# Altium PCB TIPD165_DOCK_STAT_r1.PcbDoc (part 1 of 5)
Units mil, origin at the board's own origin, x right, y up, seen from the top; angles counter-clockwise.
Board outline 6950 x 2800 mil, 2 copper layers (Primary Side, Secondary Side), stack 12.7 mil thick; 32 components, 163 nets, 1211 pads, 80 vias.
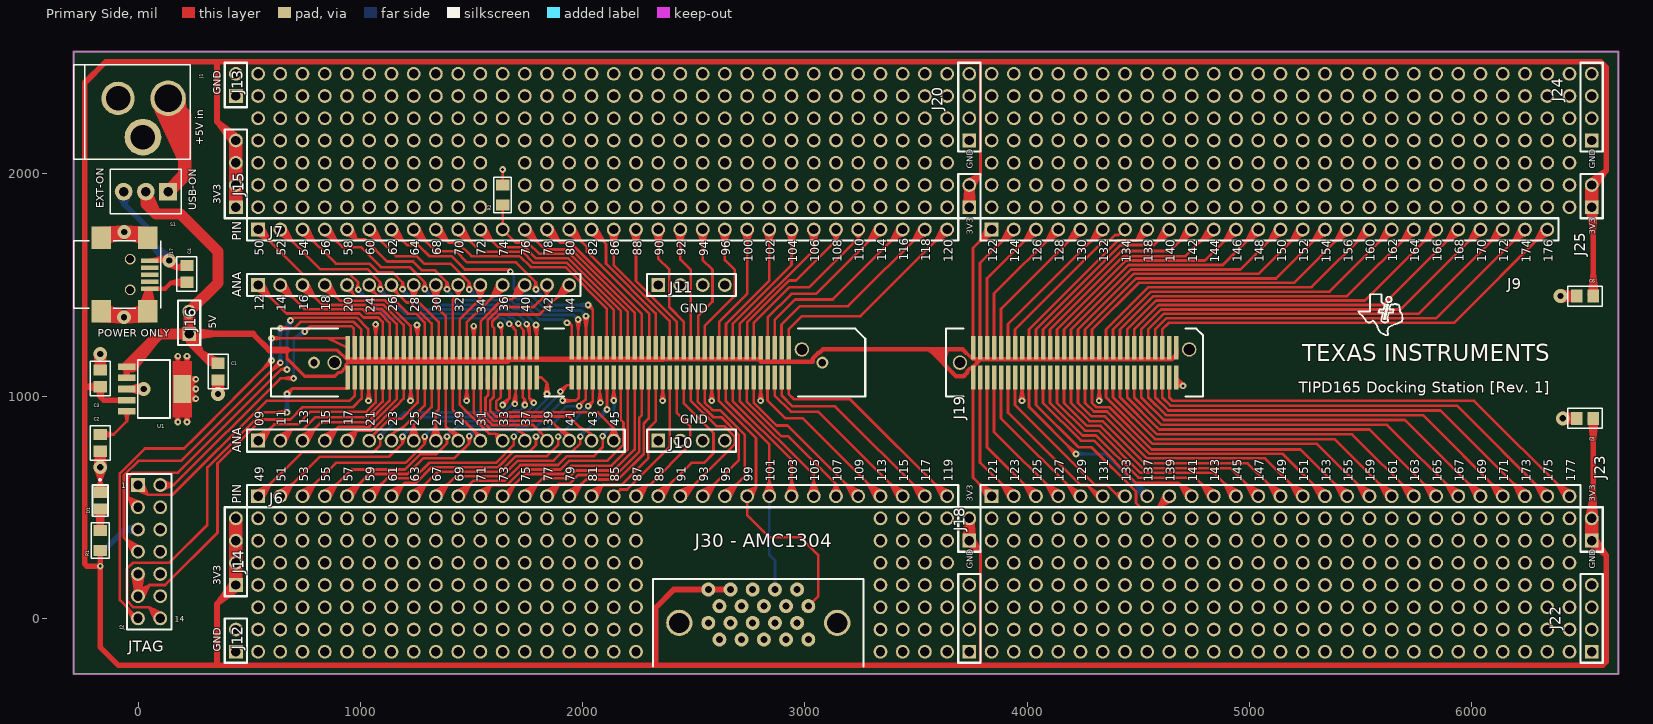
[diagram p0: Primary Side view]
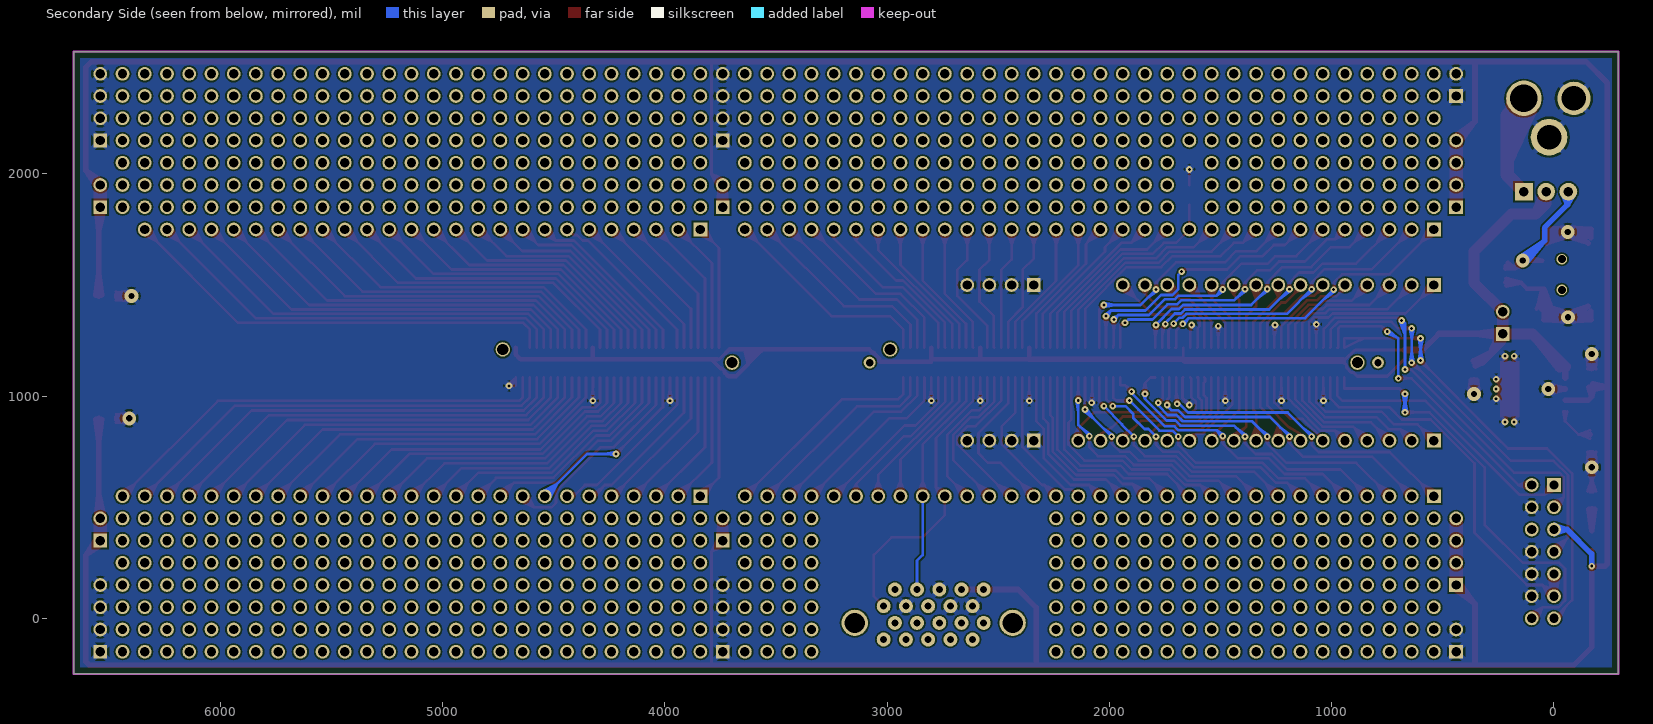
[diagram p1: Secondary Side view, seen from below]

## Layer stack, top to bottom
Primary Side: signal copper 1.35
Dielectric: dielectric 10, FR-4, Dk 4.3
Secondary Side: signal copper 1.35

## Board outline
-290,-250 6660,-250 6660,2550 -290,2550

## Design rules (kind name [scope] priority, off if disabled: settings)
Clearance "'Default' PADS rule_18" [All] p1: gap=7
Clearance "'Default' PADS rule_15" [IsVia vs IsVia] p2: gap=6
ComponentClearance "'Default' PADS rule_12" [All] p1: gap=6 collisioncheckmode=3 verticalgap=10 showdistances=FALSE
FlightTimeFalling "'Default' PADS rule_10" [All] p1: maximum=10.00
FlightTimeRising "'Default' PADS rule_9" [All] p1: maximum=10.00
Length "'Default' PADS rule_5" [All] p1: maxlimit=50000 minlimit=0
MatchedLengths "'Default' PADS rule_11" [InNetClass('All Nets')] p1: tolerance=200 checknetsindiffpair=TRUE checkdiffpairvsdiffpair=TRUE checkothers=TRUE
MaxMinImpedance "'Default' PADS rule_8" [All] p1: minimum=50.00 maximum=150.0
ParallelSegment "'Default' PADS rule_7" [All] p1: limit=1000 gap=200
ParallelSegment "'Default' PADS rule_6" [All] p2: limit=1000 gap=200
PlaneClearance "Power Plane Clearance for J8-25" [(Name='J8-25') Or (Name='J8-26') Or (Name='J8-27') Or (Name='J9-1') Or (Name='J9-2') Or (Name='J9-3') Or (Name='J9-4') Or (Name='J9-5') Or (Name='J9-6') Or (Name='J9-7') Or (Name='J9-8') Or (Name='J9-9') Or (Name='J9-10') Or (Name='J9-11') Or (Name='J9-12') Or (Name='J9-13') Or (Name='J9-14') Or (Name='J9-15') Or (Name='J9-16') Or (Name='J9-17') Or (Name='J9-18') Or (Name='J9-19') Or (Name='J9-20') Or (Name='J9-21') Or (Name='J9-22') Or (Name='J9-23') Or (Name='J9-24') Or (Name='J9-25') Or (Name='J9-26')] p1: clearance=20 // PAD - Power Plane Clearance
PlaneClearance "Power Plane Clearance for J7-3" [(Name='J7-3') Or (Name='J7-4') Or (Name='J7-5') Or (Name='J7-6') Or (Name='J7-7') Or (Name='J7-8') Or (Name='J7-9') Or (Name='J7-10') Or (Name='J7-11') Or (Name='J7-12') Or (Name='J7-13') Or (Name='J7-14') Or (Name='J7-15') Or (Name='J7-16') Or (Name='J7-17') Or (Name='J7-18') Or (Name='J7-19') Or (Name='J7-20') Or (Name='J7-21') Or (Name='J7-22') Or (Name='J7-23') Or (Name='J7-24') Or (Name='J7-25') Or (Name='J7-26') Or (Name='J7-27') Or (Name='J7-28') Or (Name='J7-29') Or (Name='J7-30') Or (Name='J7-31') Or (Name='J7-32') Or (Name='J8-1') Or (Name='J8-2') Or (Name='J8-3') Or (Name='J8-4') Or (Name='J8-5') Or (Name='J8-6') Or (Name='J8-7') Or (Name='J8-8') Or (Name='J8-9') Or (Name='J8-10') Or (Name='J8-11') Or (Name='J8-12') Or (Name='J8-13') Or (Name='J8-14') Or (Name='J8-15') Or (Name='J8-16') Or (Name='J8-17') Or (Name='J8-18') Or (Name='J8-19') Or (Name='J8-20') Or (Name='J8-21') Or (Name='J8-22') Or (Name='J8-23') Or (Name='J8-24')] p2: clearance=20 // PAD - Power Plane Clearance
PlaneClearance "Power Plane Clearance for J4-12" [(Name='J4-12') Or (Name='J4-13') Or (Name='J4-14') Or (Name='J4-15') Or (Name='J4-16') Or (Name='J4-17') Or (Name='J5-1') Or (Name='J5-2') Or (Name='J5-3') Or (Name='J5-4') Or (Name='J5-5') Or (Name='J5-6') Or (Name='J5-7') Or (Name='J5-8') Or (Name='J5-9') Or (Name='J5-10') Or (Name='J5-11') Or (Name='J5-12') Or (Name='J5-13') Or (Name='J5-14') Or (Name='J5-15') Or (Name='J6-1') Or (Name='J6-2') Or (Name='J6-3') Or (Name='J6-4') Or (Name='J6-5') Or (Name='J6-6') Or (Name='J6-7') Or (Name='J6-8') Or (Name='J6-9') Or (Name='J6-10') Or (Name='J6-11') Or (Name='J6-12') Or (Name='J6-13') Or (Name='J6-14') Or (Name='J6-15') Or (Name='J6-16') Or (Name='J6-17') Or (Name='J6-18') Or (Name='J6-19') Or (Name='J6-20') Or (Name='J6-21') Or (Name='J6-22') Or (Name='J6-23') Or (Name='J6-24') Or (Name='J6-25') Or (Name='J6-26') Or (Name='J6-27') Or (Name='J6-28') Or (Name='J6-29') Or (Name='J6-30') Or (Name='J6-31') Or (Name='J6-32') Or (Name='J7-1') Or (Name='J7-2')] p3: clearance=20 // PAD - Power Plane Clearance
PlaneClearance "Power Plane Clearance for J3-183" [(Name='J3-183') Or (Name='J3-184')] p4: clearance=10 // PAD - Power Plane Clearance
PlaneClearance "Power Plane Clearance for J29-155" [(Name='J29-155') Or (Name='J29-156') Or (Name='J29-157') Or (Name='J29-158') Or (Name='J29-159') Or (Name='J29-160') Or (Name='J29-161') Or (Name='J29-162') Or (Name='J29-163') Or (Name='J29-164') Or (Name='J29-165') Or (Name='J29-166') Or (Name='J29-167') Or (Name='J29-168') Or (Name='J29-169') Or (Name='J29-170') Or (Name='J29-171') Or (Name='J29-172') Or (Name='J29-173') Or (Name='J29-174') Or (Name='J29-175') Or (Name='J29-176') Or (Name='J29-177') Or (Name='J29-178') Or (Name='J29-179') Or (Name='J29-180') Or (Name='J29-181') Or (Name='J29-182') Or (Name='J29-183') Or (Name='J29-184') Or (Name='J29-185') Or (Name='J29-186') Or (Name='J29-187') Or (Name='J29-188') Or (Name='J29-189') Or (Name='J3-181') Or (Name='J3-182') Or (Name='J3-185') Or (Name='J3-186') Or (Name='J4-1') Or (Name='J4-2') Or (Name='J4-3') Or (Name='J4-4') Or (Name='J4-5') Or (Name='J4-6') Or (Name='J4-7') Or (Name='J4-8') Or (Name='J4-9') Or (Name='J4-10') Or (Name='J4-11')] p5: clearance=20 // PAD - Power Plane Clearance
PlaneClearance "Power Plane Clearance for J29-107" [(Name='J29-107') Or (Name='J29-108') Or (Name='J29-109') Or (Name='J29-110') Or (Name='J29-111') Or (Name='J29-112') Or (Name='J29-113') Or (Name='J29-114') Or (Name='J29-115') Or (Name='J29-116') Or (Name='J29-117') Or (Name='J29-118') Or (Name='J29-119') Or (Name='J29-120') Or (Name='J29-121') Or (Name='J29-122') Or (Name='J29-123') Or (Name='J29-124') Or (Name='J29-125') Or (Name='J29-126') Or (Name='J29-127') Or (Name='J29-128') Or (Name='J29-129') Or (Name='J29-130') Or (Name='J29-131') Or (Name='J29-132') Or (Name='J29-133') Or (Name='J29-134') Or (Name='J29-135') Or (Name='J29-136') Or (Name='J29-137') Or (Name='J29-138') Or (Name='J29-139') Or (Name='J29-140') Or (Name='J29-141') Or (Name='J29-142') Or (Name='J29-143') Or (Name='J29-144') Or (Name='J29-145') Or (Name='J29-146') Or (Name='J29-147') Or (Name='J29-148') Or (Name='J29-149') Or (Name='J29-150') Or (Name='J29-151') Or (Name='J29-152') Or (Name='J29-153') Or (Name='J29-154')] p6: clearance=20 // PAD - Power Plane Clearance
PlaneClearance "Power Plane Clearance for J29-57" [(Name='J29-57') Or (Name='J29-58') Or (Name='J29-59') Or (Name='J29-60') Or (Name='J29-61') Or (Name='J29-62') Or (Name='J29-63') Or (Name='J29-64') Or (Name='J29-65') Or (Name='J29-66') Or (Name='J29-67') Or (Name='J29-68') Or (Name='J29-69') Or (Name='J29-70') Or (Name='J29-71') Or (Name='J29-72') Or (Name='J29-73') Or (Name='J29-74') Or (Name='J29-75') Or (Name='J29-76') Or (Name='J29-77') Or (Name='J29-78') Or (Name='J29-79') Or (Name='J29-80') Or (Name='J29-81') Or (Name='J29-82') Or (Name='J29-83') Or (Name='J29-84') Or (Name='J29-85') Or (Name='J29-86') Or (Name='J29-87') Or (Name='J29-88') Or (Name='J29-89') Or (Name='J29-90') Or (Name='J29-91') Or (Name='J29-92') Or (Name='J29-93') Or (Name='J29-94') Or (Name='J29-95') Or (Name='J29-96') Or (Name='J29-97') Or (Name='J29-98') Or (Name='J29-99') Or (Name='J29-100') Or (Name='J29-101') Or (Name='J29-102') Or (Name='J29-103') Or (Name='J29-104') Or (Name='J29-105') Or (Name='J29-106')] p7: clearance=20 // PAD - Power Plane Clearance
PlaneClearance "Power Plane Clearance for J29-6" [(Name='J29-6') Or (Name='J29-7') Or (Name='J29-8') Or (Name='J29-9') Or (Name='J29-10') Or (Name='J29-11') Or (Name='J29-12') Or (Name='J29-13') Or (Name='J29-14') Or (Name='J29-15') Or (Name='J29-16') Or (Name='J29-17') Or (Name='J29-18') Or (Name='J29-19') Or (Name='J29-20') Or (Name='J29-21') Or (Name='J29-22') Or (Name='J29-23') Or (Name='J29-24') Or (Name='J29-25') Or (Name='J29-26') Or (Name='J29-27') Or (Name='J29-28') Or (Name='J29-29') Or (Name='J29-30') Or (Name='J29-31') Or (Name='J29-32') Or (Name='J29-33') Or (Name='J29-34') Or (Name='J29-35') Or (Name='J29-36') Or (Name='J29-37') Or (Name='J29-38') Or (Name='J29-39') Or (Name='J29-40') Or (Name='J29-41') Or (Name='J29-42') Or (Name='J29-43') Or (Name='J29-44') Or (Name='J29-45') Or (Name='J29-46') Or (Name='J29-47') Or (Name='J29-48') Or (Name='J29-49') Or (Name='J29-50') Or (Name='J29-51') Or (Name='J29-52') Or (Name='J29-53') Or (Name='J29-54') Or (Name='J29-55') Or (Name='J29-56')] p8: clearance=20 // PAD - Power Plane Clearance
PlaneClearance "Power Plane Clearance for J28-146" [(Name='J28-146') Or (Name='J28-147') Or (Name='J28-148') Or (Name='J28-149') Or (Name='J28-150') Or (Name='J28-151') Or (Name='J28-152') Or (Name='J28-153') Or (Name='J28-154') Or (Name='J28-155') Or (Name='J28-156') Or (Name='J28-157') Or (Name='J28-158') Or (Name='J28-159') Or (Name='J28-160') Or (Name='J28-161') Or (Name='J28-162') Or (Name='J28-163') Or (Name='J28-164') Or (Name='J28-165') Or (Name='J28-166') Or (Name='J28-167') Or (Name='J28-168') Or (Name='J28-169') Or (Name='J28-170') Or (Name='J28-171') Or (Name='J28-172') Or (Name='J28-173') Or (Name='J28-174') Or (Name='J28-175') Or (Name='J28-176') Or (Name='J28-177') Or (Name='J28-178') Or (Name='J28-179') Or (Name='J28-180') Or (Name='J28-181') Or (Name='J28-182') Or (Name='J28-183') Or (Name='J28-184') Or (Name='J28-185') Or (Name='J28-186') Or (Name='J28-187') Or (Name='J28-188') Or (Name='J28-189') Or (Name='J29-1') Or (Name='J29-2') Or (Name='J29-3') Or (Name='J29-4') Or (Name='J29-5')] p9: clearance=20 // PAD - Power Plane Clearance
PlaneClearance "Power Plane Clearance for J28-98" [(Name='J28-98') Or (Name='J28-99') Or (Name='J28-100') Or (Name='J28-101') Or (Name='J28-102') Or (Name='J28-103') Or (Name='J28-104') Or (Name='J28-105') Or (Name='J28-106') Or (Name='J28-107') Or (Name='J28-108') Or (Name='J28-109') Or (Name='J28-110') Or (Name='J28-111') Or (Name='J28-112') Or (Name='J28-113') Or (Name='J28-114') Or (Name='J28-115') Or (Name='J28-116') Or (Name='J28-117') Or (Name='J28-118') Or (Name='J28-119') Or (Name='J28-120') Or (Name='J28-121') Or (Name='J28-122') Or (Name='J28-123') Or (Name='J28-124') Or (Name='J28-125') Or (Name='J28-126') Or (Name='J28-127') Or (Name='J28-128') Or (Name='J28-129') Or (Name='J28-130') Or (Name='J28-131') Or (Name='J28-132') Or (Name='J28-133') Or (Name='J28-134') Or (Name='J28-135') Or (Name='J28-136') Or (Name='J28-137') Or (Name='J28-138') Or (Name='J28-139') Or (Name='J28-140') Or (Name='J28-141') Or (Name='J28-142') Or (Name='J28-143') Or (Name='J28-144') Or (Name='J28-145')] p10: clearance=20 // PAD - Power Plane Clearance
PlaneClearance "Power Plane Clearance for J28-47" [(Name='J28-47') Or (Name='J28-48') Or (Name='J28-49') Or (Name='J28-50') Or (Name='J28-51') Or (Name='J28-52') Or (Name='J28-53') Or (Name='J28-54') Or (Name='J28-55') Or (Name='J28-56') Or (Name='J28-57') Or (Name='J28-58') Or (Name='J28-59') Or (Name='J28-60') Or (Name='J28-61') Or (Name='J28-62') Or (Name='J28-63') Or (Name='J28-64') Or (Name='J28-65') Or (Name='J28-66') Or (Name='J28-67') Or (Name='J28-68') Or (Name='J28-69') Or (Name='J28-70') Or (Name='J28-71') Or (Name='J28-72') Or (Name='J28-73') Or (Name='J28-74') Or (Name='J28-75') Or (Name='J28-76') Or (Name='J28-77') Or (Name='J28-78') Or (Name='J28-79') Or (Name='J28-80') Or (Name='J28-81') Or (Name='J28-82') Or (Name='J28-83') Or (Name='J28-84') Or (Name='J28-85') Or (Name='J28-86') Or (Name='J28-87') Or (Name='J28-88') Or (Name='J28-89') Or (Name='J28-90') Or (Name='J28-91') Or (Name='J28-92') Or (Name='J28-93') Or (Name='J28-94') Or (Name='J28-95') Or (Name='J28-96') Or (Name='J28-97')] p11: clearance=20 // PAD - Power Plane Clearance
PlaneClearance "Power Plane Clearance for J27-221" [(Name='J27-221') Or (Name='J27-222') Or (Name='J27-223') Or (Name='J27-224')] p12: clearance=15 // PAD - Power Plane Clearance
PlaneClearance "Power Plane Clearance for J27-173" [(Name='J27-173') Or (Name='J27-174') Or (Name='J27-175') Or (Name='J27-176') Or (Name='J27-177') Or (Name='J27-178') Or (Name='J27-179') Or (Name='J27-180') Or (Name='J27-181') Or (Name='J27-182') Or (Name='J27-183') Or (Name='J27-184') Or (Name='J27-185') Or (Name='J27-186') Or (Name='J27-187') Or (Name='J27-188') Or (Name='J27-189') Or (Name='J27-190') Or (Name='J27-191') Or (Name='J27-192') Or (Name='J27-193') Or (Name='J27-194') Or (Name='J27-195') Or (Name='J27-196') Or (Name='J27-197') Or (Name='J27-198') Or (Name='J27-199') Or (Name='J27-200') Or (Name='J27-201') Or (Name='J27-202') Or (Name='J27-203') Or (Name='J27-204') Or (Name='J27-205') Or (Name='J27-206') Or (Name='J27-207') Or (Name='J27-208') Or (Name='J27-209') Or (Name='J27-210') Or (Name='J27-211') Or (Name='J27-212') Or (Name='J27-213') Or (Name='J27-214') Or (Name='J27-215') Or (Name='J27-216') Or (Name='J27-217') Or (Name='J27-218') Or (Name='J27-219') Or (Name='J27-220')] p13: clearance=15 // PAD - Power Plane Clearance
PlaneClearance "Power Plane Clearance for J27-125" [(Name='J27-125') Or (Name='J27-126') Or (Name='J27-127') Or (Name='J27-128') Or (Name='J27-129') Or (Name='J27-130') Or (Name='J27-131') Or (Name='J27-132') Or (Name='J27-133') Or (Name='J27-134') Or (Name='J27-135') Or (Name='J27-136') Or (Name='J27-137') Or (Name='J27-138') Or (Name='J27-139') Or (Name='J27-140') Or (Name='J27-141') Or (Name='J27-142') Or (Name='J27-143') Or (Name='J27-144') Or (Name='J27-145') Or (Name='J27-146') Or (Name='J27-147') Or (Name='J27-148') Or (Name='J27-149') Or (Name='J27-150') Or (Name='J27-151') Or (Name='J27-152') Or (Name='J27-153') Or (Name='J27-154') Or (Name='J27-155') Or (Name='J27-156') Or (Name='J27-157') Or (Name='J27-158') Or (Name='J27-159') Or (Name='J27-160') Or (Name='J27-161') Or (Name='J27-162') Or (Name='J27-163') Or (Name='J27-164') Or (Name='J27-165') Or (Name='J27-166') Or (Name='J27-167') Or (Name='J27-168') Or (Name='J27-169') Or (Name='J27-170') Or (Name='J27-171') Or (Name='J27-172')] p14: clearance=15 // PAD - Power Plane Clearance
PlaneClearance "Power Plane Clearance for J27-76" [(Name='J27-76') Or (Name='J27-77') Or (Name='J27-78') Or (Name='J27-79') Or (Name='J27-80') Or (Name='J27-81') Or (Name='J27-82') Or (Name='J27-83') Or (Name='J27-84') Or (Name='J27-85') Or (Name='J27-86') Or (Name='J27-87') Or (Name='J27-88') Or (Name='J27-89') Or (Name='J27-90') Or (Name='J27-91') Or (Name='J27-92') Or (Name='J27-93') Or (Name='J27-94') Or (Name='J27-95') Or (Name='J27-96') Or (Name='J27-97') Or (Name='J27-98') Or (Name='J27-99') Or (Name='J27-100') Or (Name='J27-101') Or (Name='J27-102') Or (Name='J27-103') Or (Name='J27-104') Or (Name='J27-105') Or (Name='J27-106') Or (Name='J27-107') Or (Name='J27-108') Or (Name='J27-109') Or (Name='J27-110') Or (Name='J27-111') Or (Name='J27-112') Or (Name='J27-113') Or (Name='J27-114') Or (Name='J27-115') Or (Name='J27-116') Or (Name='J27-117') Or (Name='J27-118') Or (Name='J27-119') Or (Name='J27-120') Or (Name='J27-121') Or (Name='J27-122') Or (Name='J27-123') Or (Name='J27-124')] p15: clearance=15 // PAD - Power Plane Clearance
PlaneClearance "Power Plane Clearance for J27-25" [(Name='J27-25') Or (Name='J27-26') Or (Name='J27-27') Or (Name='J27-28') Or (Name='J27-29') Or (Name='J27-30') Or (Name='J27-31') Or (Name='J27-32') Or (Name='J27-33') Or (Name='J27-34') Or (Name='J27-35') Or (Name='J27-36') Or (Name='J27-37') Or (Name='J27-38') Or (Name='J27-39') Or (Name='J27-40') Or (Name='J27-41') Or (Name='J27-42') Or (Name='J27-43') Or (Name='J27-44') Or (Name='J27-45') Or (Name='J27-46') Or (Name='J27-47') Or (Name='J27-48') Or (Name='J27-49') Or (Name='J27-50') Or (Name='J27-51') Or (Name='J27-52') Or (Name='J27-53') Or (Name='J27-54') Or (Name='J27-55') Or (Name='J27-56') Or (Name='J27-57') Or (Name='J27-58') Or (Name='J27-59') Or (Name='J27-60') Or (Name='J27-61') Or (Name='J27-62') Or (Name='J27-63') Or (Name='J27-64') Or (Name='J27-65') Or (Name='J27-66') Or (Name='J27-67') Or (Name='J27-68') Or (Name='J27-69') Or (Name='J27-70') Or (Name='J27-71') Or (Name='J27-72') Or (Name='J27-73') Or (Name='J27-74') Or (Name='J27-75')] p16: clearance=15 // PAD - Power Plane Clearance
PlaneClearance "Power Plane Clearance for J26-199" [(Name='J26-199') Or (Name='J26-200') Or (Name='J26-201') Or (Name='J26-202') Or (Name='J26-203') Or (Name='J26-204') Or (Name='J26-205') Or (Name='J26-206') Or (Name='J26-207') Or (Name='J26-208') Or (Name='J26-209') Or (Name='J26-210') Or (Name='J26-211') Or (Name='J26-212') Or (Name='J26-213') Or (Name='J26-214') Or (Name='J26-215') Or (Name='J26-216') Or (Name='J26-217') Or (Name='J26-218') Or (Name='J26-219') Or (Name='J26-220') Or (Name='J26-221') Or (Name='J26-222') Or (Name='J26-223') Or (Name='J26-224') Or (Name='J27-1') Or (Name='J27-2') Or (Name='J27-3') Or (Name='J27-4') Or (Name='J27-5') Or (Name='J27-6') Or (Name='J27-7') Or (Name='J27-8') Or (Name='J27-9') Or (Name='J27-10') Or (Name='J27-11') Or (Name='J27-12') Or (Name='J27-13') Or (Name='J27-14') Or (Name='J27-15') Or (Name='J27-16') Or (Name='J27-17') Or (Name='J27-18') Or (Name='J27-19') Or (Name='J27-20') Or (Name='J27-21') Or (Name='J27-22') Or (Name='J27-23') Or (Name='J27-24')] p17: clearance=15 // PAD - Power Plane Clearance
PlaneClearance "Power Plane Clearance for J26-151" [(Name='J26-151') Or (Name='J26-152') Or (Name='J26-153') Or (Name='J26-154') Or (Name='J26-155') Or (Name='J26-156') Or (Name='J26-157') Or (Name='J26-158') Or (Name='J26-159') Or (Name='J26-160') Or (Name='J26-161') Or (Name='J26-162') Or (Name='J26-163') Or (Name='J26-164') Or (Name='J26-165') Or (Name='J26-166') Or (Name='J26-167') Or (Name='J26-168') Or (Name='J26-169') Or (Name='J26-170') Or (Name='J26-171') Or (Name='J26-172') Or (Name='J26-173') Or (Name='J26-174') Or (Name='J26-175') Or (Name='J26-176') Or (Name='J26-177') Or (Name='J26-178') Or (Name='J26-179') Or (Name='J26-180') Or (Name='J26-181') Or (Name='J26-182') Or (Name='J26-183') Or (Name='J26-184') Or (Name='J26-185') Or (Name='J26-186') Or (Name='J26-187') Or (Name='J26-188') Or (Name='J26-189') Or (Name='J26-190') Or (Name='J26-191') Or (Name='J26-192') Or (Name='J26-193') Or (Name='J26-194') Or (Name='J26-195') Or (Name='J26-196') Or (Name='J26-197') Or (Name='J26-198')] p18: clearance=15 // PAD - Power Plane Clearance
PlaneClearance "Power Plane Clearance for J26-103" [(Name='J26-103') Or (Name='J26-104') Or (Name='J26-105') Or (Name='J26-106') Or (Name='J26-107') Or (Name='J26-108') Or (Name='J26-109') Or (Name='J26-110') Or (Name='J26-111') Or (Name='J26-112') Or (Name='J26-113') Or (Name='J26-114') Or (Name='J26-115') Or (Name='J26-116') Or (Name='J26-117') Or (Name='J26-118') Or (Name='J26-119') Or (Name='J26-120') Or (Name='J26-121') Or (Name='J26-122') Or (Name='J26-123') Or (Name='J26-124') Or (Name='J26-125') Or (Name='J26-126') Or (Name='J26-127') Or (Name='J26-128') Or (Name='J26-129') Or (Name='J26-130') Or (Name='J26-131') Or (Name='J26-132') Or (Name='J26-133') Or (Name='J26-134') Or (Name='J26-135') Or (Name='J26-136') Or (Name='J26-137') Or (Name='J26-138') Or (Name='J26-139') Or (Name='J26-140') Or (Name='J26-141') Or (Name='J26-142') Or (Name='J26-143') Or (Name='J26-144') Or (Name='J26-145') Or (Name='J26-146') Or (Name='J26-147') Or (Name='J26-148') Or (Name='J26-149') Or (Name='J26-150')] p19: clearance=15 // PAD - Power Plane Clearance
PlaneClearance "Power Plane Clearance for J26-52" [(Name='J26-52') Or (Name='J26-53') Or (Name='J26-54') Or (Name='J26-55') Or (Name='J26-56') Or (Name='J26-57') Or (Name='J26-58') Or (Name='J26-59') Or (Name='J26-60') Or (Name='J26-61') Or (Name='J26-62') Or (Name='J26-63') Or (Name='J26-64') Or (Name='J26-65') Or (Name='J26-66') Or (Name='J26-67') Or (Name='J26-68') Or (Name='J26-69') Or (Name='J26-70') Or (Name='J26-71') Or (Name='J26-72') Or (Name='J26-73') Or (Name='J26-74') Or (Name='J26-75') Or (Name='J26-76') Or (Name='J26-77') Or (Name='J26-78') Or (Name='J26-79') Or (Name='J26-80') Or (Name='J26-81') Or (Name='J26-82') Or (Name='J26-83') Or (Name='J26-84') Or (Name='J26-85') Or (Name='J26-86') Or (Name='J26-87') Or (Name='J26-88') Or (Name='J26-89') Or (Name='J26-90') Or (Name='J26-91') Or (Name='J26-92') Or (Name='J26-93') Or (Name='J26-94') Or (Name='J26-95') Or (Name='J26-96') Or (Name='J26-97') Or (Name='J26-98') Or (Name='J26-99') Or (Name='J26-100') Or (Name='J26-101') Or (Name='J26-102')] p20: clearance=15 // PAD - Power Plane Clearance
PlaneClearance "Power Plane Clearance for J26-1" [(Name='J26-1') Or (Name='J26-2') Or (Name='J26-3') Or (Name='J26-4') Or (Name='J26-5') Or (Name='J26-6') Or (Name='J26-7') Or (Name='J26-8') Or (Name='J26-9') Or (Name='J26-10') Or (Name='J26-11') Or (Name='J26-12') Or (Name='J26-13') Or (Name='J26-14') Or (Name='J26-15') Or (Name='J26-16') Or (Name='J26-17') Or (Name='J26-18') Or (Name='J26-19') Or (Name='J26-20') Or (Name='J26-21') Or (Name='J26-22') Or (Name='J26-23') Or (Name='J26-24') Or (Name='J26-25') Or (Name='J26-26') Or (Name='J26-27') Or (Name='J26-28') Or (Name='J26-29') Or (Name='J26-30') Or (Name='J26-31') Or (Name='J26-32') Or (Name='J26-33') Or (Name='J26-34') Or (Name='J26-35') Or (Name='J26-36') Or (Name='J26-37') Or (Name='J26-38') Or (Name='J26-39') Or (Name='J26-40') Or (Name='J26-41') Or (Name='J26-42') Or (Name='J26-43') Or (Name='J26-44') Or (Name='J26-45') Or (Name='J26-46') Or (Name='J26-47') Or (Name='J26-48') Or (Name='J26-49') Or (Name='J26-50') Or (Name='J26-51')] p21: clearance=15 // PAD - Power Plane Clearance
PlaneClearance "Power Plane Clearance for J24-1" [(Name='J24-1') Or (Name='J24-2') Or (Name='J24-3') Or (Name='J24-4') Or (Name='J25-1') Or (Name='J25-2') Or (Name='J28-1') Or (Name='J28-2') Or (Name='J28-3') Or (Name='J28-4') Or (Name='J28-5') Or (Name='J28-6') Or (Name='J28-7') Or (Name='J28-8') Or (Name='J28-9') Or (Name='J28-10') Or (Name='J28-11') Or (Name='J28-12') Or (Name='J28-13') Or (Name='J28-14') Or (Name='J28-15') Or (Name='J28-16') Or (Name='J28-17') Or (Name='J28-18') Or (Name='J28-19') Or (Name='J28-20') Or (Name='J28-21') Or (Name='J28-22') Or (Name='J28-23') Or (Name='J28-24') Or (Name='J28-25') Or (Name='J28-26') Or (Name='J28-27') Or (Name='J28-28') Or (Name='J28-29') Or (Name='J28-30') Or (Name='J28-31') Or (Name='J28-32') Or (Name='J28-33') Or (Name='J28-34') Or (Name='J28-35') Or (Name='J28-36') Or (Name='J28-37') Or (Name='J28-38') Or (Name='J28-39') Or (Name='J28-40') Or (Name='J28-41') Or (Name='J28-42') Or (Name='J28-43') Or (Name='J28-44') Or (Name='J28-45') Or (Name='J28-46')] p22: clearance=20 // PAD - Power Plane Clearance
PlaneClearance "Power Plane Clearance for J17-10" [(Name='J17-10') Or (Name='J17-11')] p23: clearance=17 // PAD - Power Plane Clearance
PlaneClearance "Power Plane Clearance for J10-1" [(Name='J10-1') Or (Name='J10-2') Or (Name='J10-3') Or (Name='J10-4') Or (Name='J11-1') Or (Name='J11-2') Or (Name='J11-3') Or (Name='J11-4') Or (Name='J12-1') Or (Name='J12-2') Or (Name='J13-1') Or (Name='J13-2') Or (Name='J14-1') Or (Name='J14-2') Or (Name='J14-3') Or (Name='J14-4') Or (Name='J15-1') Or (Name='J15-2') Or (Name='J15-3') Or (Name='J15-4') Or (Name='J16-1') Or (Name='J16-2') Or (Name='J18-1') Or (Name='J18-2') Or (Name='J18-3') Or (Name='J18-4') Or (Name='J19-1') Or (Name='J19-2') Or (Name='J2-1') Or (Name='J2-2') Or (Name='J2-3') Or (Name='J2-4') Or (Name='J2-5') Or (Name='J2-6') Or (Name='J2-7') Or (Name='J2-8') Or (Name='J2-9') Or (Name='J2-10') Or (Name='J2-11') Or (Name='J2-12') Or (Name='J2-13') Or (Name='J2-14') Or (Name='J20-1') Or (Name='J20-2') Or (Name='J20-3') Or (Name='J20-4') Or (Name='J21-1') Or (Name='J21-2') Or (Name='J22-1') Or (Name='J22-2') Or (Name='J22-3') Or (Name='J22-4') Or (Name='J23-1') Or (Name='J23-2')] p24: clearance=20 // PAD - Power Plane Clearance
PlaneClearance "Power Plane Clearance for J1-3" [(Name='J1-3')] p25: clearance=47.5 // PAD - Power Plane Clearance
PlaneClearance "Power Plane Clearance for J1-2" [(Name='J1-2')] p26: clearance=38 // PAD - Power Plane Clearance
PlaneClearance "Power Plane Clearance for J1-1" [(Name='J1-1')] p27: clearance=40 // PAD - Power Plane Clearance
PlaneClearance "'Default' PADS rule_14" [All] p28: clearance=15
PlaneConnect "Power Plane Connect Style for VIA_PWR" [IsVia And (ViaDiameter=62) And (HoleSize=28)] p1: planeconnectstyle=Relief reliefexpansion=11 reliefentries=4 reliefconductorwidth=17 reliefairgap=10
PlaneConnect "Power Plane Connect Style for VIA_STD" [IsVia And (ViaDiameter=30) And (HoleSize=13)] p2: planeconnectstyle=Relief reliefexpansion=11 reliefentries=4 reliefconductorwidth=12 reliefairgap=10
PlaneConnect "Power Plane Connect Style for J4-1" [(Name='J4-1')] p3: planeconnectstyle=Relief reliefexpansion=10 reliefentries=4 reliefconductorwidth=15 reliefairgap=7.5
PlaneConnect "Power Plane Connect Style - pads with no thermal_35" [(Name='J29-154') Or (Name='J29-155') Or (Name='J29-156') Or (Name='J29-157') Or (Name='J29-158') Or (Name='J29-159') Or (Name='J29-160') Or (Name='J29-161') Or (Name='J29-162') Or (Name='J29-163') Or (Name='J29-164') Or (Name='J29-165') Or (Name='J29-166') Or (Name='J29-167') Or (Name='J29-168') Or (Name='J29-169') Or (Name='J29-170') Or (Name='J29-171') Or (Name='J29-172') Or (Name='J29-173') Or (Name='J29-174') Or (Name='J29-175') Or (Name='J29-176') Or (Name='J29-177') Or (Name='J29-178') Or (Name='J29-179') Or (Name='J29-180') Or (Name='J29-181') Or (Name='J29-182') Or (Name='J29-183') Or (Name='J29-184') Or (Name='J29-185') Or (Name='J29-186') Or (Name='J29-187') Or (Name='J29-188') Or (Name='J29-189') Or (Name='J3-181') Or (Name='J3-182') Or (Name='J3-183') Or (Name='J3-184') Or (Name='J3-185') Or (Name='J3-186')] p4: planeconnectstyle=NoConnect reliefexpansion=20 reliefentries=4 reliefconductorwidth=10 reliefairgap=10 // PAD - No Thermal Connect Rule
PlaneConnect "Power Plane Connect Style - pads with no thermal_34" [(Name='J29-106') Or (Name='J29-107') Or (Name='J29-108') Or (Name='J29-109') Or (Name='J29-110') Or (Name='J29-111') Or (Name='J29-112') Or (Name='J29-113') Or (Name='J29-114') Or (Name='J29-115') Or (Name='J29-116') Or (Name='J29-117') Or (Name='J29-118') Or (Name='J29-119') Or (Name='J29-120') Or (Name='J29-121') Or (Name='J29-122') Or (Name='J29-123') Or (Name='J29-124') Or (Name='J29-125') Or (Name='J29-126') Or (Name='J29-127') Or (Name='J29-128') Or (Name='J29-129') Or (Name='J29-130') Or (Name='J29-131') Or (Name='J29-132') Or (Name='J29-133') Or (Name='J29-134') Or (Name='J29-135') Or (Name='J29-136') Or (Name='J29-137') Or (Name='J29-138') Or (Name='J29-139') Or (Name='J29-140') Or (Name='J29-141') Or (Name='J29-142') Or (Name='J29-143') Or (Name='J29-144') Or (Name='J29-145') Or (Name='J29-146') Or (Name='J29-147') Or (Name='J29-148') Or (Name='J29-149') Or (Name='J29-150') Or (Name='J29-151') Or (Name='J29-152') Or (Name='J29-153')] p5: planeconnectstyle=NoConnect reliefexpansion=20 reliefentries=4 reliefconductorwidth=10 reliefairgap=10 // PAD - No Thermal Connect Rule
PlaneConnect "Power Plane Connect Style - pads with no thermal_33" [(Name='J29-56') Or (Name='J29-57') Or (Name='J29-58') Or (Name='J29-59') Or (Name='J29-60') Or (Name='J29-61') Or (Name='J29-62') Or (Name='J29-63') Or (Name='J29-64') Or (Name='J29-65') Or (Name='J29-66') Or (Name='J29-67') Or (Name='J29-68') Or (Name='J29-69') Or (Name='J29-70') Or (Name='J29-71') Or (Name='J29-72') Or (Name='J29-73') Or (Name='J29-74') Or (Name='J29-75') Or (Name='J29-76') Or (Name='J29-77') Or (Name='J29-78') Or (Name='J29-79') Or (Name='J29-80') Or (Name='J29-81') Or (Name='J29-82') Or (Name='J29-83') Or (Name='J29-84') Or (Name='J29-85') Or (Name='J29-86') Or (Name='J29-87') Or (Name='J29-88') Or (Name='J29-89') Or (Name='J29-90') Or (Name='J29-91') Or (Name='J29-92') Or (Name='J29-93') Or (Name='J29-94') Or (Name='J29-95') Or (Name='J29-96') Or (Name='J29-97') Or (Name='J29-98') Or (Name='J29-99') Or (Name='J29-100') Or (Name='J29-101') Or (Name='J29-102') Or (Name='J29-103') Or (Name='J29-104') Or (Name='J29-105')] p6: planeconnectstyle=NoConnect reliefexpansion=20 reliefentries=4 reliefconductorwidth=10 reliefairgap=10 // PAD - No Thermal Connect Rule
PlaneConnect "Power Plane Connect Style - pads with no thermal_32" [(Name='J29-5') Or (Name='J29-6') Or (Name='J29-7') Or (Name='J29-8') Or (Name='J29-9') Or (Name='J29-10') Or (Name='J29-11') Or (Name='J29-12') Or (Name='J29-13') Or (Name='J29-14') Or (Name='J29-15') Or (Name='J29-16') Or (Name='J29-17') Or (Name='J29-18') Or (Name='J29-19') Or (Name='J29-20') Or (Name='J29-21') Or (Name='J29-22') Or (Name='J29-23') Or (Name='J29-24') Or (Name='J29-25') Or (Name='J29-26') Or (Name='J29-27') Or (Name='J29-28') Or (Name='J29-29') Or (Name='J29-30') Or (Name='J29-31') Or (Name='J29-32') Or (Name='J29-33') Or (Name='J29-34') Or (Name='J29-35') Or (Name='J29-36') Or (Name='J29-37') Or (Name='J29-38') Or (Name='J29-39') Or (Name='J29-40') Or (Name='J29-41') Or (Name='J29-42') Or (Name='J29-43') Or (Name='J29-44') Or (Name='J29-45') Or (Name='J29-46') Or (Name='J29-47') Or (Name='J29-48') Or (Name='J29-49') Or (Name='J29-50') Or (Name='J29-51') Or (Name='J29-52') Or (Name='J29-53') Or (Name='J29-54') Or (Name='J29-55')] p7: planeconnectstyle=NoConnect reliefexpansion=20 reliefentries=4 reliefconductorwidth=10 reliefairgap=10 // PAD - No Thermal Connect Rule
PlaneConnect "Power Plane Connect Style - pads with no thermal_31" [(Name='J28-145') Or (Name='J28-146') Or (Name='J28-147') Or (Name='J28-148') Or (Name='J28-149') Or (Name='J28-150') Or (Name='J28-151') Or (Name='J28-152') Or (Name='J28-153') Or (Name='J28-154') Or (Name='J28-155') Or (Name='J28-156') Or (Name='J28-157') Or (Name='J28-158') Or (Name='J28-159') Or (Name='J28-160') Or (Name='J28-161') Or (Name='J28-162') Or (Name='J28-163') Or (Name='J28-164') Or (Name='J28-165') Or (Name='J28-166') Or (Name='J28-167') Or (Name='J28-168') Or (Name='J28-169') Or (Name='J28-170') Or (Name='J28-171') Or (Name='J28-172') Or (Name='J28-173') Or (Name='J28-174') Or (Name='J28-175') Or (Name='J28-176') Or (Name='J28-177') Or (Name='J28-178') Or (Name='J28-179') Or (Name='J28-180') Or (Name='J28-181') Or (Name='J28-182') Or (Name='J28-183') Or (Name='J28-184') Or (Name='J28-185') Or (Name='J28-186') Or (Name='J28-187') Or (Name='J28-188') Or (Name='J28-189') Or (Name='J29-1') Or (Name='J29-2') Or (Name='J29-3') Or (Name='J29-4')] p8: planeconnectstyle=NoConnect reliefexpansion=20 reliefentries=4 reliefconductorwidth=10 reliefairgap=10 // PAD - No Thermal Connect Rule
PlaneConnect "Power Plane Connect Style - pads with no thermal_30" [(Name='J28-97') Or (Name='J28-98') Or (Name='J28-99') Or (Name='J28-100') Or (Name='J28-101') Or (Name='J28-102') Or (Name='J28-103') Or (Name='J28-104') Or (Name='J28-105') Or (Name='J28-106') Or (Name='J28-107') Or (Name='J28-108') Or (Name='J28-109') Or (Name='J28-110') Or (Name='J28-111') Or (Name='J28-112') Or (Name='J28-113') Or (Name='J28-114') Or (Name='J28-115') Or (Name='J28-116') Or (Name='J28-117') Or (Name='J28-118') Or (Name='J28-119') Or (Name='J28-120') Or (Name='J28-121') Or (Name='J28-122') Or (Name='J28-123') Or (Name='J28-124') Or (Name='J28-125') Or (Name='J28-126') Or (Name='J28-127') Or (Name='J28-128') Or (Name='J28-129') Or (Name='J28-130') Or (Name='J28-131') Or (Name='J28-132') Or (Name='J28-133') Or (Name='J28-134') Or (Name='J28-135') Or (Name='J28-136') Or (Name='J28-137') Or (Name='J28-138') Or (Name='J28-139') Or (Name='J28-140') Or (Name='J28-141') Or (Name='J28-142') Or (Name='J28-143') Or (Name='J28-144')] p9: planeconnectstyle=NoConnect reliefexpansion=20 reliefentries=4 reliefconductorwidth=10 reliefairgap=10 // PAD - No Thermal Connect Rule
PlaneConnect "Power Plane Connect Style - pads with no thermal_29" [(Name='J28-46') Or (Name='J28-47') Or (Name='J28-48') Or (Name='J28-49') Or (Name='J28-50') Or (Name='J28-51') Or (Name='J28-52') Or (Name='J28-53') Or (Name='J28-54') Or (Name='J28-55') Or (Name='J28-56') Or (Name='J28-57') Or (Name='J28-58') Or (Name='J28-59') Or (Name='J28-60') Or (Name='J28-61') Or (Name='J28-62') Or (Name='J28-63') Or (Name='J28-64') Or (Name='J28-65') Or (Name='J28-66') Or (Name='J28-67') Or (Name='J28-68') Or (Name='J28-69') Or (Name='J28-70') Or (Name='J28-71') Or (Name='J28-72') Or (Name='J28-73') Or (Name='J28-74') Or (Name='J28-75') Or (Name='J28-76') Or (Name='J28-77') Or (Name='J28-78') Or (Name='J28-79') Or (Name='J28-80') Or (Name='J28-81') Or (Name='J28-82') Or (Name='J28-83') Or (Name='J28-84') Or (Name='J28-85') Or (Name='J28-86') Or (Name='J28-87') Or (Name='J28-88') Or (Name='J28-89') Or (Name='J28-90') Or (Name='J28-91') Or (Name='J28-92') Or (Name='J28-93') Or (Name='J28-94') Or (Name='J28-95') Or (Name='J28-96')] p10: planeconnectstyle=NoConnect reliefexpansion=20 reliefentries=4 reliefconductorwidth=10 reliefairgap=10 // PAD - No Thermal Connect Rule
PlaneConnect "Power Plane Connect Style - pads with no thermal_28" [(Name='J27-219') Or (Name='J27-220') Or (Name='J27-221') Or (Name='J27-222') Or (Name='J27-223') Or (Name='J27-224') Or (Name='J28-1') Or (Name='J28-2') Or (Name='J28-3') Or (Name='J28-4') Or (Name='J28-5') Or (Name='J28-6') Or (Name='J28-7') Or (Name='J28-8') Or (Name='J28-9') Or (Name='J28-10') Or (Name='J28-11') Or (Name='J28-12') Or (Name='J28-13') Or (Name='J28-14') Or (Name='J28-15') Or (Name='J28-16') Or (Name='J28-17') Or (Name='J28-18') Or (Name='J28-19') Or (Name='J28-20') Or (Name='J28-21') Or (Name='J28-22') Or (Name='J28-23') Or (Name='J28-24') Or (Name='J28-25') Or (Name='J28-26') Or (Name='J28-27') Or (Name='J28-28') Or (Name='J28-29') Or (Name='J28-30') Or (Name='J28-31') Or (Name='J28-32') Or (Name='J28-33') Or (Name='J28-34') Or (Name='J28-35') Or (Name='J28-36') Or (Name='J28-37') Or (Name='J28-38') Or (Name='J28-39') Or (Name='J28-40') Or (Name='J28-41') Or (Name='J28-42') Or (Name='J28-43') Or (Name='J28-44') Or (Name='J28-45')] p11: planeconnectstyle=NoConnect reliefexpansion=20 reliefentries=4 reliefconductorwidth=10 reliefairgap=10 // PAD - No Thermal Connect Rule
PlaneConnect "Power Plane Connect Style - pads with no thermal_27" [(Name='J27-171') Or (Name='J27-172') Or (Name='J27-173') Or (Name='J27-174') Or (Name='J27-175') Or (Name='J27-176') Or (Name='J27-177') Or (Name='J27-178') Or (Name='J27-179') Or (Name='J27-180') Or (Name='J27-181') Or (Name='J27-182') Or (Name='J27-183') Or (Name='J27-184') Or (Name='J27-185') Or (Name='J27-186') Or (Name='J27-187') Or (Name='J27-188') Or (Name='J27-189') Or (Name='J27-190') Or (Name='J27-191') Or (Name='J27-192') Or (Name='J27-193') Or (Name='J27-194') Or (Name='J27-195') Or (Name='J27-196') Or (Name='J27-197') Or (Name='J27-198') Or (Name='J27-199') Or (Name='J27-200') Or (Name='J27-201') Or (Name='J27-202') Or (Name='J27-203') Or (Name='J27-204') Or (Name='J27-205') Or (Name='J27-206') Or (Name='J27-207') Or (Name='J27-208') Or (Name='J27-209') Or (Name='J27-210') Or (Name='J27-211') Or (Name='J27-212') Or (Name='J27-213') Or (Name='J27-214') Or (Name='J27-215') Or (Name='J27-216') Or (Name='J27-217') Or (Name='J27-218')] p12: planeconnectstyle=NoConnect reliefexpansion=20 reliefentries=4 reliefconductorwidth=10 reliefairgap=10 // PAD - No Thermal Connect Rule
PlaneConnect "Power Plane Connect Style - pads with no thermal_26" [(Name='J27-123') Or (Name='J27-124') Or (Name='J27-125') Or (Name='J27-126') Or (Name='J27-127') Or (Name='J27-128') Or (Name='J27-129') Or (Name='J27-130') Or (Name='J27-131') Or (Name='J27-132') Or (Name='J27-133') Or (Name='J27-134') Or (Name='J27-135') Or (Name='J27-136') Or (Name='J27-137') Or (Name='J27-138') Or (Name='J27-139') Or (Name='J27-140') Or (Name='J27-141') Or (Name='J27-142') Or (Name='J27-143') Or (Name='J27-144') Or (Name='J27-145') Or (Name='J27-146') Or (Name='J27-147') Or (Name='J27-148') Or (Name='J27-149') Or (Name='J27-150') Or (Name='J27-151') Or (Name='J27-152') Or (Name='J27-153') Or (Name='J27-154') Or (Name='J27-155') Or (Name='J27-156') Or (Name='J27-157') Or (Name='J27-158') Or (Name='J27-159') Or (Name='J27-160') Or (Name='J27-161') Or (Name='J27-162') Or (Name='J27-163') Or (Name='J27-164') Or (Name='J27-165') Or (Name='J27-166') Or (Name='J27-167') Or (Name='J27-168') Or (Name='J27-169') Or (Name='J27-170')] p13: planeconnectstyle=NoConnect reliefexpansion=20 reliefentries=4 reliefconductorwidth=10 reliefairgap=10 // PAD - No Thermal Connect Rule
PlaneConnect "Power Plane Connect Style - pads with no thermal_25" [(Name='J27-73') Or (Name='J27-74') Or (Name='J27-75') Or (Name='J27-76') Or (Name='J27-77') Or (Name='J27-78') Or (Name='J27-79') Or (Name='J27-80') Or (Name='J27-81') Or (Name='J27-82') Or (Name='J27-83') Or (Name='J27-84') Or (Name='J27-85') Or (Name='J27-86') Or (Name='J27-87') Or (Name='J27-88') Or (Name='J27-89') Or (Name='J27-90') Or (Name='J27-91') Or (Name='J27-92') Or (Name='J27-93') Or (Name='J27-94') Or (Name='J27-95') Or (Name='J27-96') Or (Name='J27-97') Or (Name='J27-98') Or (Name='J27-99') Or (Name='J27-100') Or (Name='J27-101') Or (Name='J27-102') Or (Name='J27-103') Or (Name='J27-104') Or (Name='J27-105') Or (Name='J27-106') Or (Name='J27-107') Or (Name='J27-108') Or (Name='J27-109') Or (Name='J27-110') Or (Name='J27-111') Or (Name='J27-112') Or (Name='J27-113') Or (Name='J27-114') Or (Name='J27-115') Or (Name='J27-116') Or (Name='J27-117') Or (Name='J27-118') Or (Name='J27-119') Or (Name='J27-120') Or (Name='J27-121') Or (Name='J27-122')] p14: planeconnectstyle=NoConnect reliefexpansion=20 reliefentries=4 reliefconductorwidth=10 reliefairgap=10 // PAD - No Thermal Connect Rule
PlaneConnect "Power Plane Connect Style - pads with no thermal_24" [(Name='J27-22') Or (Name='J27-23') Or (Name='J27-24') Or (Name='J27-25') Or (Name='J27-26') Or (Name='J27-27') Or (Name='J27-28') Or (Name='J27-29') Or (Name='J27-30') Or (Name='J27-31') Or (Name='J27-32') Or (Name='J27-33') Or (Name='J27-34') Or (Name='J27-35') Or (Name='J27-36') Or (Name='J27-37') Or (Name='J27-38') Or (Name='J27-39') Or (Name='J27-40') Or (Name='J27-41') Or (Name='J27-42') Or (Name='J27-43') Or (Name='J27-44') Or (Name='J27-45') Or (Name='J27-46') Or (Name='J27-47') Or (Name='J27-48') Or (Name='J27-49') Or (Name='J27-50') Or (Name='J27-51') Or (Name='J27-52') Or (Name='J27-53') Or (Name='J27-54') Or (Name='J27-55') Or (Name='J27-56') Or (Name='J27-57') Or (Name='J27-58') Or (Name='J27-59') Or (Name='J27-60') Or (Name='J27-61') Or (Name='J27-62') Or (Name='J27-63') Or (Name='J27-64') Or (Name='J27-65') Or (Name='J27-66') Or (Name='J27-67') Or (Name='J27-68') Or (Name='J27-69') Or (Name='J27-70') Or (Name='J27-71') Or (Name='J27-72')] p15: planeconnectstyle=NoConnect reliefexpansion=20 reliefentries=4 reliefconductorwidth=10 reliefairgap=10 // PAD - No Thermal Connect Rule
PlaneConnect "Power Plane Connect Style - pads with no thermal_23" [(Name='J26-196') Or (Name='J26-197') Or (Name='J26-198') Or (Name='J26-199') Or (Name='J26-200') Or (Name='J26-201') Or (Name='J26-202') Or (Name='J26-203') Or (Name='J26-204') Or (Name='J26-205') Or (Name='J26-206') Or (Name='J26-207') Or (Name='J26-208') Or (Name='J26-209') Or (Name='J26-210') Or (Name='J26-211') Or (Name='J26-212') Or (Name='J26-213') Or (Name='J26-214') Or (Name='J26-215') Or (Name='J26-216') Or (Name='J26-217') Or (Name='J26-218') Or (Name='J26-219') Or (Name='J26-220') Or (Name='J26-221') Or (Name='J26-222') Or (Name='J26-223') Or (Name='J26-224') Or (Name='J27-1') Or (Name='J27-2') Or (Name='J27-3') Or (Name='J27-4') Or (Name='J27-5') Or (Name='J27-6') Or (Name='J27-7') Or (Name='J27-8') Or (Name='J27-9') Or (Name='J27-10') Or (Name='J27-11') Or (Name='J27-12') Or (Name='J27-13') Or (Name='J27-14') Or (Name='J27-15') Or (Name='J27-16') Or (Name='J27-17') Or (Name='J27-18') Or (Name='J27-19') Or (Name='J27-20') Or (Name='J27-21')] p16: planeconnectstyle=NoConnect reliefexpansion=20 reliefentries=4 reliefconductorwidth=10 reliefairgap=10 // PAD - No Thermal Connect Rule
PlaneConnect "Power Plane Connect Style - pads with no thermal_22" [(Name='J26-148') Or (Name='J26-149') Or (Name='J26-150') Or (Name='J26-151') Or (Name='J26-152') Or (Name='J26-153') Or (Name='J26-154') Or (Name='J26-155') Or (Name='J26-156') Or (Name='J26-157') Or (Name='J26-158') Or (Name='J26-159') Or (Name='J26-160') Or (Name='J26-161') Or (Name='J26-162') Or (Name='J26-163') Or (Name='J26-164') Or (Name='J26-165') Or (Name='J26-166') Or (Name='J26-167') Or (Name='J26-168') Or (Name='J26-169') Or (Name='J26-170') Or (Name='J26-171') Or (Name='J26-172') Or (Name='J26-173') Or (Name='J26-174') Or (Name='J26-175') Or (Name='J26-176') Or (Name='J26-177') Or (Name='J26-178') Or (Name='J26-179') Or (Name='J26-180') Or (Name='J26-181') Or (Name='J26-182') Or (Name='J26-183') Or (Name='J26-184') Or (Name='J26-185') Or (Name='J26-186') Or (Name='J26-187') Or (Name='J26-188') Or (Name='J26-189') Or (Name='J26-190') Or (Name='J26-191') Or (Name='J26-192') Or (Name='J26-193') Or (Name='J26-194') Or (Name='J26-195')] p17: planeconnectstyle=NoConnect reliefexpansion=20 reliefentries=4 reliefconductorwidth=10 reliefairgap=10 // PAD - No Thermal Connect Rule
PlaneConnect "Power Plane Connect Style - pads with no thermal_21" [(Name='J26-100') Or (Name='J26-101') Or (Name='J26-102') Or (Name='J26-103') Or (Name='J26-104') Or (Name='J26-105') Or (Name='J26-106') Or (Name='J26-107') Or (Name='J26-108') Or (Name='J26-109') Or (Name='J26-110') Or (Name='J26-111') Or (Name='J26-112') Or (Name='J26-113') Or (Name='J26-114') Or (Name='J26-115') Or (Name='J26-116') Or (Name='J26-117') Or (Name='J26-118') Or (Name='J26-119') Or (Name='J26-120') Or (Name='J26-121') Or (Name='J26-122') Or (Name='J26-123') Or (Name='J26-124') Or (Name='J26-125') Or (Name='J26-126') Or (Name='J26-127') Or (Name='J26-128') Or (Name='J26-129') Or (Name='J26-130') Or (Name='J26-131') Or (Name='J26-132') Or (Name='J26-133') Or (Name='J26-134') Or (Name='J26-135') Or (Name='J26-136') Or (Name='J26-137') Or (Name='J26-138') Or (Name='J26-139') Or (Name='J26-140') Or (Name='J26-141') Or (Name='J26-142') Or (Name='J26-143') Or (Name='J26-144') Or (Name='J26-145') Or (Name='J26-146') Or (Name='J26-147')] p18: planeconnectstyle=NoConnect reliefexpansion=20 reliefentries=4 reliefconductorwidth=10 reliefairgap=10 // PAD - No Thermal Connect Rule
PlaneConnect "Power Plane Connect Style - pads with no thermal_20" [(Name='J26-49') Or (Name='J26-50') Or (Name='J26-51') Or (Name='J26-52') Or (Name='J26-53') Or (Name='J26-54') Or (Name='J26-55') Or (Name='J26-56') Or (Name='J26-57') Or (Name='J26-58') Or (Name='J26-59') Or (Name='J26-60') Or (Name='J26-61') Or (Name='J26-62') Or (Name='J26-63') Or (Name='J26-64') Or (Name='J26-65') Or (Name='J26-66') Or (Name='J26-67') Or (Name='J26-68') Or (Name='J26-69') Or (Name='J26-70') Or (Name='J26-71') Or (Name='J26-72') Or (Name='J26-73') Or (Name='J26-74') Or (Name='J26-75') Or (Name='J26-76') Or (Name='J26-77') Or (Name='J26-78') Or (Name='J26-79') Or (Name='J26-80') Or (Name='J26-81') Or (Name='J26-82') Or (Name='J26-83') Or (Name='J26-84') Or (Name='J26-85') Or (Name='J26-86') Or (Name='J26-87') Or (Name='J26-88') Or (Name='J26-89') Or (Name='J26-90') Or (Name='J26-91') Or (Name='J26-92') Or (Name='J26-93') Or (Name='J26-94') Or (Name='J26-95') Or (Name='J26-96') Or (Name='J26-97') Or (Name='J26-98') Or (Name='J26-99')] p19: planeconnectstyle=NoConnect reliefexpansion=20 reliefentries=4 reliefconductorwidth=10 reliefairgap=10 // PAD - No Thermal Connect Rule
PlaneConnect "Power Plane Connect Style - pads with no thermal" [(Name='J17-10') Or (Name='J17-11') Or (Name='J2-6') Or (Name='J26-1') Or (Name='J26-2') Or (Name='J26-3') Or (Name='J26-4') Or (Name='J26-5') Or (Name='J26-6') Or (Name='J26-7') Or (Name='J26-8') Or (Name='J26-9') Or (Name='J26-10') Or (Name='J26-11') Or (Name='J26-12') Or (Name='J26-13') Or (Name='J26-14') Or (Name='J26-15') Or (Name='J26-16') Or (Name='J26-17') Or (Name='J26-18') Or (Name='J26-19') Or (Name='J26-20') Or (Name='J26-21') Or (Name='J26-22') Or (Name='J26-23') Or (Name='J26-24') Or (Name='J26-25') Or (Name='J26-26') Or (Name='J26-27') Or (Name='J26-28') Or (Name='J26-29') Or (Name='J26-30') Or (Name='J26-31') Or (Name='J26-32') Or (Name='J26-33') Or (Name='J26-34') Or (Name='J26-35') Or (Name='J26-36') Or (Name='J26-37') Or (Name='J26-38') Or (Name='J26-39') Or (Name='J26-40') Or (Name='J26-41') Or (Name='J26-42') Or (Name='J26-43') Or (Name='J26-44') Or (Name='J26-45') Or (Name='J26-46') Or (Name='J26-47') Or (Name='J26-48')] p20: planeconnectstyle=NoConnect reliefexpansion=20 reliefentries=4 reliefconductorwidth=10 reliefairgap=10 // PAD - No Thermal Connect Rule
PlaneConnect "Power Plane Connect Style for J10-1" [(Name='J10-1')] p21: planeconnectstyle=Relief reliefexpansion=10 reliefentries=4 reliefconductorwidth=20 reliefairgap=10
PlaneConnect "Power Plane Connect Style for J1-3" [(Name='J1-3')] p22: planeconnectstyle=Relief reliefexpansion=27.5 reliefentries=4 reliefconductorwidth=60 reliefairgap=20
PlaneConnect "Power Plane Connect Style for J1-2" [(Name='J1-2')] p23: planeconnectstyle=Relief reliefexpansion=18 reliefentries=4 reliefconductorwidth=55 reliefairgap=20
PlaneConnect "Power Plane Connect Style for J1-1" [(Name='J1-1')] p24: planeconnectstyle=Relief reliefexpansion=20 reliefentries=4 reliefconductorwidth=50 reliefairgap=20
PlaneConnect "Power Plane Connect Style - Via from round thru-hole global defaults" [IsVia] p25: planeconnectstyle=Relief reliefexpansion=20 reliefentries=4 reliefconductorwidth=25 reliefairgap=10
PlaneConnect "Power Plane Connect Style - Round thru-hole pad from global defaults" [IsPad And OnMultiLayer And (PadShape_MidLayer1 = 'Round') And (PadXSize_MidLayer1 = PadYSize_MidLayer1)] p26: planeconnectstyle=Relief reliefexpansion=20 reliefentries=4 reliefconductorwidth=25 reliefairgap=10
PlaneConnect "Power Plane Connect Style - Square thru-hole pad from global defaults" [IsPad And OnMultiLayer And ((PadShape_MidLayer1 = 'Rectangular') Or (PadShape_MidLayer1 = 'Octagonal') Or (PadShape_MidLayer1 = 'Rounded Rectangle')) And (PadXSize_MidLayer1 = PadYSize_MidLayer1)] p27: planeconnectstyle=Relief reliefexpansion=20 reliefentries=4 reliefconductorwidth=25 reliefairgap=10
PlaneConnect "Power Plane Connect Style - Rect thru-hole pad from global defaults" [IsPad And OnMultiLayer And ((PadShape_MidLayer1 = 'Rectangular') Or (PadShape_MidLayer1 = 'Octagonal') Or (PadShape_MidLayer1 = 'Rounded Rectangle')) And (PadXSize_MidLayer1 <> PadYSize_MidLayer1)] p28: planeconnectstyle=Direct reliefexpansion=20 reliefentries=4 reliefconductorwidth=25 reliefairgap=10
PlaneConnect "Power Plane Connect Style - Square-rect thru-hole pad from global defaults" [IsPad And OnMultiLayer And (PadShape_MidLayer1 = 'Rounded Rectangle') And (PadXSize_MidLayer1 = PadYSize_MidLayer1) And (Pad_CornerRadius_MidLayer1 = '0%')] p29: planeconnectstyle=Direct reliefexpansion=20 reliefentries=4 reliefconductorwidth=25 reliefairgap=10
PlaneConnect "Power Plane Connect Style - Oval thru-hole pad from global defaults" [IsPad And OnMultiLayer And (PadShape_MidLayer1 = 'Round') And (PadXSize_MidLayer1 <> PadYSize_MidLayer1)] p30: planeconnectstyle=Relief reliefexpansion=20 reliefentries=4 reliefconductorwidth=25 reliefairgap=10
PlaneConnect "Power Plane Connect Style - Round-oval thru-hole pad from global defaults" [IsPad And OnMultiLayer And (PadShape_MidLayer1 = 'Rounded Rectangle') And (PadXSize_MidLayer1 = PadYSize_MidLayer1) And (Pad_CornerRadius_MidLayer1 = '100%')] p31: planeconnectstyle=Relief reliefexpansion=20 reliefentries=4 reliefconductorwidth=25 reliefairgap=10
PolygonConnect "Polygon Connect Style - Secondary Side Round SMD from global defaults" [IsSMTPin And (PadShape_BottomLayer = 'Round') And (PadXSize_BottomLayer = PADYSize_BottomLayer) vs Layer = 'Secondary Side'] p1: connectstyle=NoConnect reliefconductorwidth=10 reliefentries=4 polygonreliefangle="45 Angle" airgapwidth=10
PolygonConnect "Polygon Connect Style - Primary Side Round SMD from global defaults" [IsSMTPin And (PadShape_TopLayer = 'Round') And (PadXSize_TopLayer = PADYSize_TopLayer) vs Layer = 'Primary Side'] p2: connectstyle=NoConnect reliefconductorwidth=10 reliefentries=4 polygonreliefangle="45 Angle" airgapwidth=10
PolygonConnect "Polygon Connect Style - Secondary Side Square SMD from global defaults 1" [IsSMTPin And (PadShape_BottomLayer = 'Rectangular') And (PadXSize_BottomLayer = PADYSize_BottomLayer) vs Layer = 'Secondary Side'] p3: connectstyle=Relief reliefconductorwidth=10 reliefentries=4 polygonreliefangle="45 Angle" airgapwidth=10
PolygonConnect "Polygon Connect Style - Secondary Side Square SMD from global defaults 2" [IsSMTPin And (PadShape_BottomLayer = 'Octagonal') And (PadXSize_BottomLayer = PADYSize_BottomLayer) vs Layer = 'Secondary Side'] p4: connectstyle=Relief reliefconductorwidth=10 reliefentries=4 polygonreliefangle="45 Angle" airgapwidth=10
PolygonConnect "Polygon Connect Style - Secondary Side Square SMD from global defaults 3" [IsSMTPin And (PadShape_BottomLayer = 'Rounded Rectangle') And (PadXSize_BottomLayer = PADYSize_BottomLayer) vs Layer = 'Secondary Side'] p5: connectstyle=Relief reliefconductorwidth=10 reliefentries=4 polygonreliefangle="45 Angle" airgapwidth=10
